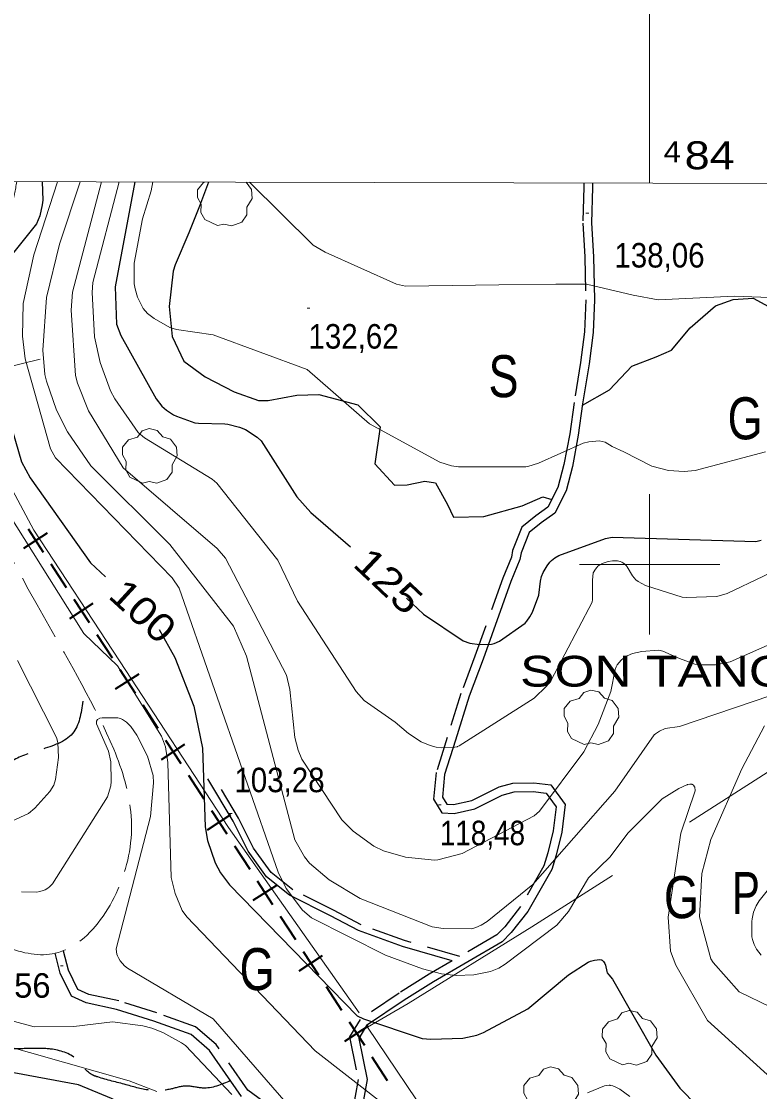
# Model space of a CAD drawing. Extents: x 480264 to 484872, y 4381275 to 4384491.
# Drawn here: x 483775.7 to 484039.3, y 4383811.8 to 4384193.8 of the extents above; entities that cross this region are included whole.
import ezdxf
from ezdxf.enums import TextEntityAlignment as Align

# ---------------------------------------------------------------- set-up
doc = ezdxf.new("R2010")
doc.units = 0
doc.header["$LTSCALE"] = 4
for name, pattern in [('DOTTED', [1.5, 0.3, -1.2]), ('LONG_DASHED', [7.5, 6, -1.5]), ('MEDIUM_DASHED', [4.5, 3, -1.5])]:
    doc.linetypes.add(name, pattern=pattern)
for name, color, linetype, lineweight in [('1', 7, 'Continuous', 13), ('15', 7, 'LONG_DASHED', 13), ('2', 7, 'DOTTED', 13), ('25', 7, 'LONG_DASHED', 25), ('29', 7, 'Continuous', 13), ('34', 7, 'Continuous', 35), ('38', 7, 'Continuous', 25), ('51', 7, 'Continuous', 13), ('7', 7, 'Continuous', 13), ('8', 7, 'Continuous', 25), ('9', 7, 'Continuous', 13)]:
    doc.layers.add(name, color=color, linetype=linetype, lineweight=lineweight)
doc.layers.add('31', color=7, linetype='Continuous')
doc.layers.add('5', color=7, linetype='Continuous')

msp = doc.modelspace()

# ---------------------------------------------------------------- linework, layer by layer
at = {"layer": '1'}
for p, q in [((484000, 4384136.04), (484000, 4384207.49)), ((484000, 4384025), (484000, 4383975)), ((483975, 4384000), (484025, 4384000))]:
    msp.add_line(p, q, dxfattribs=at)
msp.add_lwpolyline([(480523.1, 4384144.4), (484100.5, 4384135.8), (484095.6, 4381823.6), (480517.1, 4381832.1)], close=True, dxfattribs=at)
at = {"layer": '15'}
msp.add_spline([(483774.04, 4384136.58), (483772.3, 4384127.81), (483752.25, 4384071.22), (483756.85, 4384038.64), (483803.38, 4383945.39), (483814.24, 4383897.42), (483787.76, 4383861.18), (483751.06, 4383870.8), (483688.08, 4383884.15), (483625.18, 4383934.22), (483597.18, 4383948.46)], degree=3, dxfattribs=at)
at = {"layer": '25'}
for points in [[(483842.45, 4384136.42), (483839.27, 4384127.84), (483835.42, 4384118.33), (483830.59, 4384106.92), (483829.9, 4384104.66), (483828.5, 4384092.06), (483829.47, 4384081.3), (483833.63, 4384072.53), (483841.31, 4384066.97), (483851.63, 4384061.53), (483860.31, 4384058.46), (483863.75, 4384058.43), (483873.97, 4384060.33), (483881.83, 4384060.66), (483895.82, 4384056.96), (483903.75, 4384049.05), (483901.86, 4384035.91), (483908.88, 4384028.22), (483913.47, 4384028.34), (483919.71, 4384029.69), (483923.54, 4384029.11), (483927.81, 4384021.31), (483929.95, 4384016.86), (483940.75, 4384017.13), (483954.45, 4384020.94), (483961.91, 4384024.05), (483965.08, 4384023.11)], [(483976.02, 4384056.77), (483985.65, 4384062.3), (483993.65, 4384070.71), (484002.35, 4384074.07), (484007.8, 4384076.43), (484014.46, 4384084.36), (484023.48, 4384092.27), (484029.76, 4384094.57), (484036.98, 4384095.01), (484050.75, 4384087.43), (484052.84, 4384085.91), (484062.14, 4384076.21), (484062.95, 4384063.12), (484068.39, 4384055.89), (484082.38, 4384055.04), (484100.25, 4384050.57), (484100.32, 4384050.55)]]:
    msp.add_lwpolyline(points, dxfattribs=at)
at = {"layer": '29'}
for points in [[(483845.73, 4384120.91), (483841.19, 4384123.03), (483839.78, 4384125.57), (483839.88, 4384128.55), (483838.51, 4384130.96), (483838.55, 4384133.71), (483840.71, 4384136.31), (483841.07, 4384136.42), (483841.08, 4384136.42), (483841.09, 4384136.42), (483841.1, 4384136.42), (483841.11, 4384136.42), (483841.12, 4384136.42), (483841.13, 4384136.42), (483841.14, 4384136.42), (483841.15, 4384136.42), (483841.16, 4384136.42), (483841.17, 4384136.42), (483841.18, 4384136.42), (483841.19, 4384136.42), (483841.2, 4384136.42), (483841.21, 4384136.42), (483841.22, 4384136.42)], [(483855.89, 4384136.39), (483857.87, 4384133.74), (483858.11, 4384130.61), (483856.23, 4384127.46), (483856.23, 4384124.78), (483854.41, 4384122.17), (483850.79, 4384120.83), (483848.02, 4384121.46), (483845.73, 4384120.91)]]:
    msp.add_lwpolyline(points, dxfattribs=at)
for points in [[(483818.97, 4384029.02), (483814.43, 4384031.14), (483813.02, 4384033.68), (483813.12, 4384036.66), (483811.75, 4384039.07), (483811.79, 4384041.82), (483813.95, 4384044.42), (483817.14, 4384045.42), (483818.79, 4384047.61), (483821.36, 4384048.44), (483824.22, 4384047.79), (483826.17, 4384045.52), (483828.98, 4384044.7), (483831.11, 4384041.85), (483831.35, 4384038.72), (483829.47, 4384035.57), (483829.47, 4384032.89), (483827.65, 4384030.28), (483824.03, 4384028.94), (483821.26, 4384029.57)], [(483976.65, 4383935.73), (483972.11, 4383937.85), (483970.7, 4383940.39), (483970.8, 4383943.37), (483969.43, 4383945.78), (483969.47, 4383948.53), (483971.63, 4383951.13), (483974.82, 4383952.13), (483976.47, 4383954.32), (483979.04, 4383955.15), (483981.9, 4383954.5), (483983.85, 4383952.23), (483986.66, 4383951.41), (483988.79, 4383948.56), (483989.03, 4383945.43), (483987.15, 4383942.28), (483987.15, 4383939.6), (483985.33, 4383936.99), (483981.71, 4383935.65), (483978.94, 4383936.28)], [(483990.3, 4383821.37), (483985.76, 4383823.49), (483984.35, 4383826.03), (483984.45, 4383829.01), (483983.08, 4383831.42), (483983.12, 4383834.17), (483985.28, 4383836.77), (483988.47, 4383837.77), (483990.12, 4383839.96), (483992.69, 4383840.79), (483995.55, 4383840.14), (483997.5, 4383837.87), (484000.31, 4383837.05), (484002.44, 4383834.2), (484002.68, 4383831.07), (484000.8, 4383827.92), (484000.8, 4383825.24), (483998.98, 4383822.63), (483995.36, 4383821.29), (483992.59, 4383821.92)], [(483962.24, 4383801.23), (483957.7, 4383803.35), (483956.29, 4383805.89), (483956.39, 4383808.87), (483955.02, 4383811.28), (483955.06, 4383814.03), (483957.22, 4383816.63), (483960.41, 4383817.63), (483962.06, 4383819.82), (483964.63, 4383820.65), (483967.49, 4383820), (483969.44, 4383817.73), (483972.25, 4383816.91), (483974.38, 4383814.06), (483974.62, 4383810.93), (483972.74, 4383807.78), (483972.74, 4383805.1), (483970.92, 4383802.49), (483967.3, 4383801.15), (483964.53, 4383801.78)]]:
    msp.add_lwpolyline(points, close=True, dxfattribs=at)
at = {"layer": '34'}
for p, q in [((483776.59, 4384005.79), (483784.97, 4384011.25)), ((483778.05, 4384012.71), (483783.51, 4384004.33)), ((483786.24, 4384000.14), (483791.7, 4383991.76)), ((483794.43, 4383987.57), (483799.88, 4383979.2)), ((483792.97, 4383980.66), (483801.34, 4383986.11)), ((483802.61, 4383975.01), (483808.07, 4383966.63)), ((483809.34, 4383955.52), (483817.72, 4383960.98)), ((483810.8, 4383962.44), (483816.26, 4383954.06)), ((483818.99, 4383949.87), (483824.45, 4383941.49)), ((483827.17, 4383937.3), (483832.63, 4383928.92)), ((483825.71, 4383930.38), (483834.09, 4383935.84)), ((483835.36, 4383924.73), (483840.82, 4383916.35)), ((483842.09, 4383905.24), (483850.47, 4383910.7)), ((483843.55, 4383912.16), (483849.01, 4383903.78)), ((483851.74, 4383899.59), (483857.19, 4383891.21)), ((483858.46, 4383880.11), (483866.84, 4383885.56)), ((483859.92, 4383887.03), (483865.38, 4383878.65)), ((483868.11, 4383874.46), (483873.57, 4383866.08)), ((483876.3, 4383861.89), (483881.76, 4383853.51)), ((483874.84, 4383854.97), (483883.22, 4383860.43)), ((483884.48, 4383849.32), (483889.94, 4383840.94)), ((483891.21, 4383829.83), (483899.59, 4383835.29)), ((483892.67, 4383836.75), (483898.13, 4383828.37)), ((483900.86, 4383824.18), (483906.32, 4383815.8))]:
    msp.add_line(p, q, dxfattribs=at)
at = {"layer": '38'}
for points in [[(483979.55, 4384136.09), (483979.54, 4384134.55), (483979.23, 4384121.83), (483979.97, 4384109.72), (483980.29, 4384094.35), (483979.79, 4384082.72), (483978.38, 4384071.55), (483976.08, 4384057.28), (483974.53, 4384046.06), (483972.42, 4384034.95), (483970.18, 4384026.28), (483966.09, 4384018.29), (483961.27, 4384014.82), (483957, 4384011.32), (483954.08, 4384004.1), (483953.7, 4384001.68), (483950.41, 4383993.89), (483940.52, 4383966.17), (483935.57, 4383952.91), (483930.64, 4383937.24), (483926.81, 4383925.03), (483925.99, 4383916.89), (483927.55, 4383914.36), (483929.92, 4383914.25), (483936.52, 4383915.69), (483946.26, 4383920.57), (483951.17, 4383921.87), (483958.6, 4383922.04), (483964.76, 4383921.3), (483969.81, 4383914.28), (483968.63, 4383904.36), (483966.66, 4383896.22), (483965.07, 4383891.12), (483956.52, 4383876.1), (483950.59, 4383868.61), (483947.4, 4383865.31), (483922.83, 4383851.04), (483912.31, 4383844.42), (483898.91, 4383835.43), (483896.15, 4383830.8), (483899.13, 4383816.13), (483894.92, 4383793.02)], [(483929.52, 4383858.51), (483911.74, 4383863.64), (483896.07, 4383869.32), (483886.06, 4383874.59), (483871.4, 4383881.96), (483863.19, 4383888.52), (483856.62, 4383897.58), (483851.3, 4383908.33), (483842.26, 4383923.48)], [(483854.33, 4383810.11), (483842.87, 4383826.52), (483836.27, 4383832.22), (483823.02, 4383837), (483809.7, 4383841.18), (483798.81, 4383843.48), (483793.56, 4383845.85), (483789.55, 4383854.09), (483787.76, 4383861.18)]]:
    msp.add_lwpolyline(points, dxfattribs=at)
at = {"layer": '38', "linetype": 'MEDIUM_DASHED'}
for points in [[(483976.45, 4384136.1), (483976.44, 4384134.59), (483976.13, 4384121.77), (483976.87, 4384109.6), (483977.19, 4384094.39), (483976.7, 4384082.98), (483975.31, 4384071.99), (483973.02, 4384057.74), (483971.47, 4384046.56), (483969.4, 4384035.62), (483967.26, 4384027.39), (483963.67, 4384020.36), (483959.38, 4384017.28), (483954.42, 4384013.22), (483951.08, 4384004.93), (483950.7, 4384002.53), (483947.52, 4383995.01), (483937.6, 4383967.23), (483932.63, 4383953.92), (483927.68, 4383938.17), (483923.76, 4383925.66), (483922.8, 4383916.16), (483925.77, 4383911.34), (483930.18, 4383911.13), (483937.56, 4383912.75), (483947.36, 4383917.65), (483951.61, 4383918.78), (483958.45, 4383918.94), (483963.04, 4383918.38), (483966.59, 4383913.45), (483965.57, 4383904.91), (483963.67, 4383897.05), (483962.21, 4383892.36), (483953.94, 4383877.84), (483948.26, 4383870.66), (483945.47, 4383867.77), (483932.18, 4383860.06)], [(483932.18, 4383860.06), (483912.43, 4383865.76), (483896.97, 4383871.37), (483887.08, 4383876.57), (483872.61, 4383883.85), (483864.82, 4383890.08), (483858.53, 4383898.73), (483853.26, 4383909.4), (483844.17, 4383924.63)], [(483929.52, 4383858.51), (483921.23, 4383853.7), (483910.62, 4383847.02), (483896.6, 4383837.62), (483892.87, 4383831.35), (483895.97, 4383816.09), (483892.41, 4383796.53), (483888.87, 4383797.07), (483876.72, 4383802.81), (483861.91, 4383808.36), (483856.58, 4383812.3), (483845.19, 4383828.61), (483837.87, 4383834.94), (483824.01, 4383839.94), (483810.49, 4383844.18), (483799.78, 4383846.44), (483795.85, 4383848.22), (483792.47, 4383855.16), (483790.76, 4383861.93)]]:
    msp.add_lwpolyline(points, dxfattribs=at)
at = {"layer": '38', "linetype": 'LONG_DASHED'}
for points in [[(483797.66, 4383951.17), (483793.94, 4383939.62), (483782.58, 4383933.86), (483772.51, 4383929.97), (483770.17, 4383928.58), (483754.92, 4383923.1), (483741.24, 4383923.21), (483727.68, 4383925.92), (483721.77, 4383928.84), (483715.08, 4383933.95), (483711.23, 4383937.31), (483702.92, 4383945.47), (483695.07, 4383953.18), (483686.77, 4383961.97), (483680.22, 4383965.97), (483667.51, 4383970.39), (483653.15, 4383975.04), (483642.98, 4383978.25), (483638.27, 4383979.87), (483633.14, 4383979.37), (483631.91, 4383977.45), (483629.73, 4383969.68), (483631.28, 4383961.7), (483633.49, 4383958.73), (483632.86, 4383954.55), (483629.24, 4383952.11), (483622.28, 4383948.05), (483615.53, 4383942.43), (483614.16, 4383940.81)], [(483850.38, 4383815.76), (483840.34, 4383813.09), (483834.51, 4383813.8), (483828.87, 4383812.7), (483821.91, 4383812.28), (483813.07, 4383814.28), (483802.92, 4383817.05), (483800.8, 4383817.91), (483795.39, 4383823.33), (483786.11, 4383827), (483779.48, 4383827.24), (483771.92, 4383827.1), (483746.93, 4383834.81), (483740.72, 4383838.99), (483730.16, 4383841.49), (483718.36, 4383846.12), (483708.26, 4383848.58), (483696.29, 4383852.18), (483684.4, 4383851.93), (483676.99, 4383853.05), (483661.51, 4383855.77), (483649.66, 4383855.69), (483640.48, 4383860.56), (483635.27, 4383865.78), (483625.84, 4383871.49), (483615.73, 4383875.12), (483610.77, 4383880), (483605.63, 4383891.18), (483601.86, 4383895.27), (483594.49, 4383900.86), (483591.05, 4383907.68), (483595.47, 4383915.22), (483601.34, 4383922.14), (483606.08, 4383931.96), (483614.16, 4383940.81)]]:
    msp.add_spline(points, degree=3, dxfattribs=at)
at = {"layer": '51'}
msp.add_line((483755.42, 4384066.52), (483782.35, 4384073.24), dxfattribs=at)
for points in [[(483896.23, 4383839.99), (483849.67, 4383906.12), (483810.74, 4383965.6), (483780.08, 4384012.22), (483764.86, 4384040.57), (483759.24, 4384049.75)], [(484014.17, 4383907.95), (484075.62, 4383947.28), (484100.13, 4383963.44)], [(483986.74, 4383889), (483957.89, 4383870.69), (483913.72, 4383843.25), (483899.21, 4383834.8), (483923.65, 4383798.71), (483943.24, 4383770.31), (483969.36, 4383729.72), (483989.5, 4383693.34), (484005.24, 4383665.31), (484033, 4383619.4), (484067.74, 4383563.28), (484088.88, 4383530.13), (484099.22, 4383531.84)]]:
    msp.add_lwpolyline(points, dxfattribs=at)
at = {"layer": '7'}
for p, q in [((483977.24, 4384125.32), (483978.24, 4384125.32)), ((483877.68, 4384091.37), (483878.68, 4384091.37)), ((483924.6, 4383914.13), (483925.6, 4383914.13)), ((483849.92, 4383911.04), (483850.92, 4383911.04)), ((483789.59, 4383856.71), (483790.59, 4383856.71))]:
    msp.add_line(p, q, dxfattribs=at)
at = {"layer": '8'}
for points in [[(483783.09, 4384136.56), (483783.35, 4384129.95), (483783.16, 4384128.33), (483782.26, 4384124.39), (483781.08, 4384121.49)], [(483816.14, 4384136.48), (483809.12, 4384099.1), (483809.61, 4384085.71), (483811.18, 4384081.64), (483823.78, 4384059.04), (483825.86, 4384056.51), (483827.48, 4384055.07), (483829.96, 4384053.38), (483831.03, 4384052.86), (483837.56, 4384050.49), (483838.95, 4384050.33), (483848.32, 4384050.14), (483849.45, 4384049.98), (483853.59, 4384048.96), (483855.66, 4384048.11), (483859.92, 4384045.37), (483861.27, 4384044.13), (483874.08, 4384024.15), (483879.06, 4384018.52), (483893.24, 4384006.28)], [(483781.08, 4384121.49), (483766.18, 4384103.11), (483765.55, 4384102.04), (483764.45, 4384099.61), (483762.52, 4384092.41), (483762.03, 4384087.4), (483762.39, 4384081.99), (483775.72, 4384036.64), (483778.8, 4384030.92), (483800.4, 4384000.51), (483805.77, 4383995.58)], [(483913.24, 4383987.97), (483919.29, 4383982.25), (483933.41, 4383972.67), (483935.8, 4383971.93), (483939.23, 4383971.39), (483943.57, 4383971.57), (483944.5, 4383971.81), (483946.35, 4383972.64), (483955.57, 4383979.06), (483956.2, 4383979.76), (483957.26, 4383981.22), (483958.2, 4383982.93), (483960.39, 4383988.97), (483960.99, 4383994.01), (483961.44, 4383995.69), (483961.99, 4383997.09), (483963.36, 4383999.49), (483964.35, 4384000.74), (483965.01, 4384001.38), (483966.13, 4384002.27), (483967.56, 4384003.1), (483984.19, 4384009.25), (483986.58, 4384009.76), (484037.96, 4384008.15), (484039.78, 4384008.58)], [(483824.9, 4383976.76), (483830.48, 4383966.73), (483837.21, 4383949.35), (483840.33, 4383934.37), (483841.26, 4383906.34), (483842.17, 4383901.46), (483844.86, 4383893.5), (483846.72, 4383889.86), (483849.97, 4383885.62), (483895.54, 4383838.82), (483897.88, 4383837.76), (483918.82, 4383830.83), (483921.85, 4383830.53), (483933.3, 4383830.86), (483938.34, 4383831.95), (483940.67, 4383832.87), (483956.47, 4383841.42), (483970.99, 4383853.45), (483978.1, 4383858.04), (483978.9, 4383858.33), (483980.35, 4383858.71), (483982.27, 4383858.97), (483982.76, 4383858.86), (483982.9, 4383858.79), (483983.04, 4383858.7), (483983.56, 4383858.23), (483984, 4383857.51), (483984.19, 4383857), (483984.67, 4383854.73), (483984.88, 4383854.21), (483985.4, 4383853.47), (483986.73, 4383851.97), (484002.16, 4383824.88), (484010.77, 4383813.06), (484016.97, 4383806.72)], [(483847.11, 4383789.7), (483832.64, 4383795.9), (483807.9, 4383809.41), (483796.02, 4383814.29), (483693.92, 4383833.16), (483614.49, 4383878.44), (483608.15, 4383880.87), (483605.14, 4383880.98)]]:
    msp.add_lwpolyline(points, dxfattribs=at)
at = {"layer": '9'}
for points in [[(483788.55, 4384136.55), (483780.1, 4384110.42), (483776.33, 4384093.04), (483776.05, 4384081.48), (483777.09, 4384073.37), (483786.08, 4384041.28), (483787.86, 4384038.06), (483829.55, 4383995.18), (483832.03, 4383991.48), (483867.35, 4383890.09), (483870.19, 4383884.36), (483876.01, 4383876.6), (483879.28, 4383873.83), (483905.72, 4383860.47), (483918.87, 4383855.61), (483925.7, 4383853.89), (483930.9, 4383853.28), (483937.27, 4383853.45), (483943.16, 4383854.65), (483946.18, 4383855.92), (483948.42, 4383857.28), (483966.86, 4383871.23), (483971.07, 4383876.11), (483978.16, 4383888.13), (483985.93, 4383895.59), (483992.23, 4383904.04), (484004.52, 4383916.3), (484010.37, 4383920.01), (484013.24, 4383921.35), (484013.29, 4383921.35), (484013.31, 4383921.34), (484013.35, 4383921.35), (484013.47, 4383921.38), (484014.4, 4383921.52), (484015, 4383921.52), (484015.14, 4383921.49), (484015.26, 4383921.44), (484015.63, 4383921.17), (484016.07, 4383920.63), (484016.12, 4383920.5), (484016.13, 4383920.44), (484016.22, 4383919.34), (484016.2, 4383919.18), (484011.17, 4383904.09), (484006.63, 4383874.04), (484007.4, 4383862), (484009.4, 4383857.01), (484020.68, 4383837.19), (484068.41, 4383793.99)], [(484043.27, 4383953.18), (484010.66, 4383942.14), (484005.55, 4383941.38), (484005.54, 4383941.38), (484003.51, 4383940.47), (484002.09, 4383939.53), (484001.63, 4383939.17), (483987.54, 4383919.01), (483958.32, 4383885.76), (483941.99, 4383872.56), (483939.79, 4383871.18), (483937.99, 4383870.37), (483936.48, 4383869.96), (483926.27, 4383870.02), (483922.33, 4383870.59), (483896.65, 4383880.69), (483885.52, 4383887.42), (483878.61, 4383893.38), (483876.81, 4383895.61), (483873.31, 4383901.7), (483856.01, 4383967.27), (483851.39, 4383977.94), (483828.63, 4384007.11), (483800.42, 4384035.15), (483792.18, 4384047.29), (483788.2, 4384054.98), (483784.66, 4384065.34), (483784.1, 4384067.74), (483783.34, 4384076.45), (483784.7, 4384095.2), (483789.26, 4384114.28), (483796.61, 4384136.53)], [(483845.53, 4384005.67), (483811.98, 4384034.49), (483799.59, 4384054.79), (483795.75, 4384064.66), (483794.97, 4384067.44), (483793.5, 4384090.74), (483793.96, 4384097.19), (483804.31, 4384136.51)], [(483810.59, 4384136.5), (483801.14, 4384100.55), (483800.93, 4384096.99), (483801.81, 4384081.18), (483803.8, 4384071.99), (483807.53, 4384061.96), (483809.1, 4384059.13), (483817.42, 4384047.04), (483819.67, 4384045.13), (483843.77, 4384030.39), (483845.42, 4384028.97), (483867.3, 4384001.47), (483874.3, 4383986.85), (483895.23, 4383954.61), (483898.06, 4383951.38), (483909.18, 4383943.63), (483913.9, 4383939.69), (483918.44, 4383936.69), (483921.66, 4383935.34), (483923.75, 4383934.81), (483925.74, 4383934.55), (483929.72, 4383934.58), (483931.14, 4383934.83), (483931.27, 4383934.88), (483931.4, 4383934.95), (483932.02, 4383935.19), (483958.72, 4383952.21), (483963.17, 4383956.5), (483964.79, 4383958.61), (483979.43, 4383986.49), (483979.56, 4383987.51), (483979.59, 4383994.39), (483979.86, 4383996.92), (483980.61, 4383998.32), (483981.1, 4383998.91), (483981.53, 4383999.33), (483982.27, 4383999.88), (483983.05, 4384000.28), (483985.19, 4384000.98), (483986.79, 4384001.22), (483988.5, 4384001.21), (483989.47, 4384001.02), (483990.07, 4384000.78), (483990.41, 4384000.6), (483991.01, 4384000.16), (483991.61, 4383999.56), (483991.94, 4383999.14), (483993.87, 4383995.96), (483995.1, 4383994.52), (483995.93, 4383993.85), (483998.53, 4383992.5), (484011.65, 4383988.28), (484013.06, 4383988.18), (484023.96, 4383988.49), (484027.72, 4383989.59), (484053.65, 4384001.92)], [(483822.63, 4384136.47), (483821.99, 4384133.36), (483818.87, 4384123.26), (483815.99, 4384107.44), (483815.91, 4384100.15), (483816.27, 4384098.3), (483817.18, 4384095.39), (483819.11, 4384091.26), (483820.66, 4384089.56), (483823.11, 4384087.69), (483828.7, 4384084.54), (483831.02, 4384083.87), (483844.18, 4384081.93), (483877.74, 4384069.59), (483899.93, 4384050.1), (483925.05, 4384036.44), (483929.28, 4384035.18), (483931.76, 4384034.81), (483955.82, 4384034.81), (483956.51, 4384034.95), (483960.29, 4384036.07), (483976.3, 4384043.23), (483978.33, 4384043.73), (483981.95, 4384044.09), (483984.17, 4384043.6), (483986.64, 4384042.03), (483986.65, 4384042.01), (483990.8, 4384040.19), (484000.77, 4384034.99), (484006.76, 4384033.51), (484012.34, 4384033.13), (484016.24, 4384033.52), (484041.38, 4384040.16)], [(484100.4, 4384088.99), (484091.98, 4384091.04), (484064.59, 4384094.39), (484030.34, 4384095.72), (484003.06, 4384094.39), (483994.09, 4384096.06), (483977.46, 4384100.05), (483966.48, 4384100.05), (483946.2, 4384099.72), (483912.84, 4384099.29), (483909.63, 4384099.96), (483884.13, 4384111.42), (483879.89, 4384113.89), (483857.14, 4384136.39)], [(483770.85, 4384018.5), (483797.94, 4383975.3), (483809.96, 4383963.78), (483825.74, 4383938.7), (483827.12, 4383934.9), (483828, 4383929.28), (483829.19, 4383888.29), (483830.62, 4383882.49), (483833.05, 4383876.5), (483834.7, 4383874.23), (483880.58, 4383826.37), (483906.35, 4383806.3)], [(484049.25, 4383974.27), (484028.74, 4383965.21), (484023.52, 4383964.19), (484018.11, 4383964.09), (484016.12, 4383964.39), (484010.65, 4383966.35), (484004.73, 4383969.07), (484003.73, 4383969.3), (484003.08, 4383969.37), (483997.16, 4383968.91), (483993.93, 4383968.15), (483991.92, 4383967.32), (483990.68, 4383966.55), (483989.83, 4383965.81), (483988.44, 4383964.1), (483988.01, 4383963.38), (483987.65, 4383962.53), (483986.12, 4383954.58), (483981.62, 4383942.79), (483976.5, 4383933.14), (483960.7, 4383911.94), (483958.81, 4383910.27), (483933.01, 4383896.77), (483924.41, 4383894.53), (483923.23, 4383894.38), (483912.88, 4383895.53), (483904.94, 4383897.8), (483901.57, 4383899.41), (483894.13, 4383904.81), (483890.05, 4383908.82), (483875.79, 4383930.46), (483874.47, 4383933.72), (483873.34, 4383938.21), (483871.52, 4383955.35), (483870.29, 4383960.45), (483848.53, 4384002.19), (483845.53, 4384005.67)], [(483769.39, 4383907.07), (483778.26, 4383911.12), (483780.53, 4383912.95), (483785.84, 4383918.9), (483787.21, 4383921.25), (483787.89, 4383923.16), (483788.91, 4383931.03), (483788.64, 4383936.43), (483788.18, 4383938.15), (483774.25, 4383965.63)], [(483775.68, 4383883.09), (483781.21, 4383883.04), (483782.21, 4383883.21), (483783.46, 4383883.56), (483784.12, 4383883.85), (483785.1, 4383884.41), (483785.72, 4383884.88), (483786.78, 4383885.94), (483806.44, 4383916.98), (483807.61, 4383920.93), (483807.76, 4383922.47), (483807.56, 4383929.58), (483806.76, 4383933.35), (483802.49, 4383943.03), (483802.46, 4383943.64), (483802.49, 4383943.81), (483802.53, 4383943.98), (483802.84, 4383944.6), (483803.71, 4383945.09), (483804.58, 4383945.25), (483810.08, 4383945.21), (483811.08, 4383945.02), (483811.83, 4383944.64), (483813.16, 4383943.69), (483814.77, 4383942.15)], [(483814.77, 4383942.15), (483816.87, 4383939.01), (483820.7, 4383931.57), (483822.75, 4383924.67), (483822.91, 4383922.04), (483821.84, 4383910)], [(484099.82, 4383814.59), (484031.98, 4383847.38), (484022.7, 4383857.91), (484021.81, 4383859.23), (484017.8, 4383874.26), (484018.68, 4383889.67), (484021.82, 4383901.76), (484032.88, 4383927.03), (484041.05, 4383942.37)], [(483821.84, 4383910), (483809.55, 4383862.82), (483809.61, 4383861.73), (483809.79, 4383860.85), (483810, 4383860.23), (483810.45, 4383859.29), (483810.99, 4383858.45), (483812.49, 4383856.75), (483813.54, 4383855.88), (483844.17, 4383837.81), (483871.71, 4383806.04)], [(483814.14, 4383815.73), (483648.24, 4383862.82), (483606.37, 4383895.17), (483601.11, 4383897.94), (483588.85, 4383897.84)], [(484039.85, 4383860.56), (484038.2, 4383862.66), (484037.31, 4383864.3), (484036.71, 4383866.13), (484036.53, 4383867.05), (484036.48, 4383872.54), (484036.56, 4383873.49), (484037.11, 4383875.81), (484038.02, 4383878.11), (484039.11, 4383879.92), (484052.64, 4383896.92)], [(483850.77, 4383810.74), (483834.23, 4383828.23), (483832.81, 4383829.25), (483826.15, 4383832.93), (483822.27, 4383834.49), (483819.02, 4383835.35), (483808.23, 4383836.78), (483794.42, 4383835.1), (483780.29, 4383834.89), (483674.95, 4383863.49)], [(483824.03, 4383811.83), (483814.14, 4383815.73)], [(483977.85, 4383811.39), (483983.84, 4383813.87), (483985.56, 4383814.07), (483985.78, 4383814.08), (483985.96, 4383814.06), (483986.83, 4383813.87), (483987.63, 4383813.56), (483989.31, 4383812.66), (483992.95, 4383810.09)]]:
    msp.add_lwpolyline(points, dxfattribs=at)

# ---------------------------------------------------------------- texts
at = {"layer": '2'}
for s, height, width, p in [('4', 7.5, 1.1, (484004.98, 4384143.53)), ('84  ', 10, 1.2, (484012.48, 4384141.01))]:
    msp.add_text(s, height=height, rotation=359.862, dxfattribs=dict(at, width=width)).set_placement(p)
at = {"layer": '31'}
for s, width, p in [('S', 0.8, (483947.825, 4384059.66)), ('G', 0.8, (484034.07, 4384044.62)), ('G', 0.8, (484011.35, 4383873.7)), ('P', 0.75, (484034.36, 4383875.19)), ('G', 0.8, (483859.83, 4383848.04))]:
    msp.add_text(s, height=15, dxfattribs=dict(at, width=width)).set_placement(p, align=Align.CENTER)
at = {"layer": '5', "width": 1.25}
msp.add_text('SON TANO VELL', height=11, dxfattribs=at).set_placement((483953.74, 4383956.36))
at = {"layer": '7'}
for s, width, p in [('138,06', 0.9, (483987.4, 4384105.93)), ('132,62', 0.9, (483878.18, 4384077)), ('103,28', 0.9, (483851.73, 4383918.68)), ('118,48', 0.85, (483925.1, 4383899.76))]:
    msp.add_text(s, height=8.75, dxfattribs=dict(at, width=width)).set_placement(p)
msp.add_text('86,56', height=8.75, dxfattribs=at).set_placement((483756.83, 4383845.34))
at = {"layer": '8'}
for s, rotation, width, p in [('125', 316.626, 1.2, (483903.331, 4383990.449)), ('100', 317.41, 1.15, (483815.701, 4383979.648))]:
    msp.add_text(s, height=10, rotation=rotation, dxfattribs=dict(at, width=width)).set_placement(p, align=Align.CENTER)

doc.saveas('drawing.dxf')
